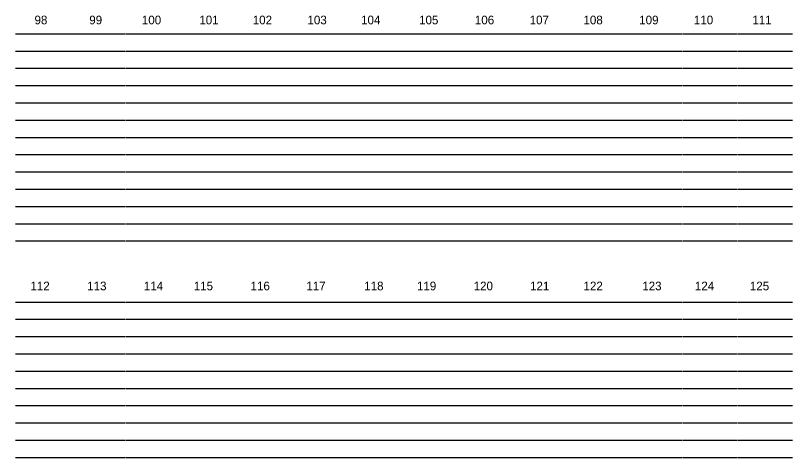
# Model space of a CAD drawing. Extents: x 11193 to 12507, y 10092 to 10555.
# Drawn here: x 11449.1 to 11644.1, y 10442.7 to 10553.6 of the extents above; entities that cross this region are included whole.
import ezdxf

# ---------------------------------------------------------------- set-up
doc = ezdxf.new("R2010")
doc.units = 0
doc.layers.add('Level 2', color=7, linetype='Continuous')

msp = doc.modelspace()

# ---------------------------------------------------------------- linework, layer by layer
at = {"layer": 'Level 2'}
for p, q in [((11449.15, 10549.04), (11463.08, 10549.04)), ((11463.2, 10549.04), (11476.76, 10549.04)), ((11476.87, 10549.04), (11490.84, 10549.04)), ((11490.96, 10549.04), (11504.92, 10549.04)), ((11505.04, 10549.04), (11518.81, 10549.04)), ((11518.92, 10549.04), (11532.69, 10549.04)), ((11532.79, 10549.04), (11546.77, 10549.04)), ((11546.87, 10549.04), (11560.65, 10549.04)), ((11560.75, 10549.04), (11574.74, 10549.04)), ((11574.84, 10549.04), (11588.61, 10549.04)), ((11588.71, 10549.04), (11602.29, 10549.04)), ((11602.39, 10549.04), (11616.37, 10549.04)), ((11616.47, 10549.04), (11630.25, 10549.04)), ((11630.36, 10549.04), (11644.09, 10549.04)), ((11449.15, 10544.71), (11463.08, 10544.71)), ((11463.2, 10544.71), (11476.76, 10544.71)), ((11476.87, 10544.71), (11490.84, 10544.71)), ((11490.96, 10544.71), (11504.92, 10544.71)), ((11505.04, 10544.71), (11518.81, 10544.71)), ((11518.92, 10544.71), (11532.69, 10544.71)), ((11532.79, 10544.71), (11546.77, 10544.71)), ((11546.87, 10544.71), (11560.65, 10544.71)), ((11560.75, 10544.71), (11574.74, 10544.71)), ((11574.84, 10544.71), (11588.61, 10544.71)), ((11588.71, 10544.71), (11602.29, 10544.71)), ((11602.39, 10544.71), (11616.37, 10544.71)), ((11616.47, 10544.71), (11630.25, 10544.71)), ((11630.36, 10544.71), (11644.09, 10544.71)), ((11449.15, 10540.37), (11463.08, 10540.37)), ((11463.2, 10540.37), (11476.76, 10540.37)), ((11476.87, 10540.37), (11490.84, 10540.37)), ((11490.96, 10540.37), (11504.92, 10540.37)), ((11505.04, 10540.37), (11518.81, 10540.37)), ((11518.92, 10540.37), (11532.69, 10540.37)), ((11532.79, 10540.37), (11546.77, 10540.37)), ((11546.87, 10540.37), (11560.65, 10540.37)), ((11560.75, 10540.37), (11574.74, 10540.37)), ((11574.84, 10540.37), (11588.61, 10540.37)), ((11588.71, 10540.37), (11602.29, 10540.37)), ((11602.39, 10540.37), (11616.37, 10540.37)), ((11616.47, 10540.37), (11630.25, 10540.37)), ((11630.36, 10540.37), (11644.09, 10540.37)), ((11449.15, 10536.04), (11463.08, 10536.04)), ((11463.2, 10536.04), (11476.76, 10536.04)), ((11476.87, 10536.04), (11490.84, 10536.04)), ((11490.96, 10536.04), (11504.92, 10536.04)), ((11505.04, 10536.04), (11518.81, 10536.04)), ((11518.92, 10536.04), (11532.69, 10536.04)), ((11532.79, 10536.04), (11546.77, 10536.04)), ((11546.87, 10536.04), (11560.65, 10536.04)), ((11560.75, 10536.04), (11574.74, 10536.04)), ((11574.84, 10536.04), (11588.61, 10536.04)), ((11588.71, 10536.04), (11602.29, 10536.04)), ((11602.39, 10536.04), (11616.37, 10536.04)), ((11616.47, 10536.04), (11630.25, 10536.04)), ((11630.36, 10536.04), (11644.09, 10536.04)), ((11449.15, 10531.71), (11463.08, 10531.71)), ((11463.2, 10531.71), (11476.76, 10531.71)), ((11476.87, 10531.71), (11490.84, 10531.71)), ((11490.96, 10531.71), (11504.92, 10531.71)), ((11505.04, 10531.71), (11518.81, 10531.71)), ((11518.92, 10531.71), (11532.69, 10531.71)), ((11532.79, 10531.71), (11546.77, 10531.71)), ((11546.87, 10531.71), (11560.65, 10531.71)), ((11560.75, 10531.71), (11574.74, 10531.71)), ((11574.84, 10531.71), (11588.61, 10531.71)), ((11588.71, 10531.71), (11602.29, 10531.71)), ((11602.39, 10531.71), (11616.37, 10531.71)), ((11616.47, 10531.71), (11630.25, 10531.71)), ((11630.36, 10531.71), (11644.09, 10531.71)), ((11449.15, 10527.38), (11463.08, 10527.38)), ((11463.2, 10527.38), (11476.76, 10527.38)), ((11476.87, 10527.38), (11490.84, 10527.38)), ((11490.96, 10527.38), (11504.92, 10527.38)), ((11505.04, 10527.38), (11518.81, 10527.38)), ((11518.92, 10527.38), (11532.69, 10527.38)), ((11532.79, 10527.38), (11546.77, 10527.38)), ((11546.87, 10527.38), (11560.65, 10527.38)), ((11560.75, 10527.38), (11574.74, 10527.38)), ((11574.84, 10527.38), (11588.61, 10527.38)), ((11588.71, 10527.38), (11602.29, 10527.38)), ((11602.39, 10527.38), (11616.37, 10527.38)), ((11616.47, 10527.38), (11630.25, 10527.38)), ((11630.36, 10527.38), (11644.09, 10527.38)), ((11449.15, 10523.05), (11463.08, 10523.05)), ((11463.2, 10523.05), (11476.76, 10523.05)), ((11476.87, 10523.05), (11490.84, 10523.05)), ((11490.96, 10523.05), (11504.92, 10523.05)), ((11505.04, 10523.05), (11518.81, 10523.05)), ((11518.92, 10523.05), (11532.69, 10523.05)), ((11532.79, 10523.05), (11546.77, 10523.05)), ((11546.87, 10523.05), (11560.65, 10523.05)), ((11560.75, 10523.05), (11574.74, 10523.05)), ((11574.84, 10523.05), (11588.61, 10523.05)), ((11588.71, 10523.05), (11602.29, 10523.05)), ((11602.39, 10523.05), (11616.37, 10523.05)), ((11616.47, 10523.05), (11630.25, 10523.05)), ((11630.36, 10523.05), (11644.09, 10523.05)), ((11449.15, 10518.71), (11463.08, 10518.71)), ((11463.2, 10518.71), (11476.76, 10518.71)), ((11476.87, 10518.71), (11490.84, 10518.71)), ((11490.96, 10518.71), (11504.92, 10518.71)), ((11505.04, 10518.71), (11518.81, 10518.71)), ((11518.92, 10518.71), (11532.69, 10518.71)), ((11532.79, 10518.71), (11546.77, 10518.71)), ((11546.87, 10518.71), (11560.65, 10518.71)), ((11560.75, 10518.71), (11574.74, 10518.71)), ((11574.84, 10518.71), (11588.61, 10518.71)), ((11588.71, 10518.71), (11602.29, 10518.71)), ((11602.39, 10518.71), (11616.37, 10518.71)), ((11616.47, 10518.71), (11630.25, 10518.71)), ((11630.36, 10518.71), (11644.09, 10518.71)), ((11449.15, 10514.38), (11463.08, 10514.38)), ((11463.2, 10514.38), (11476.76, 10514.38)), ((11476.87, 10514.38), (11490.84, 10514.38)), ((11490.96, 10514.38), (11504.92, 10514.38)), ((11505.04, 10514.38), (11518.81, 10514.38)), ((11518.92, 10514.38), (11532.69, 10514.38)), ((11532.79, 10514.38), (11546.77, 10514.38)), ((11546.87, 10514.38), (11560.65, 10514.38)), ((11560.75, 10514.38), (11574.74, 10514.38)), ((11574.84, 10514.38), (11588.61, 10514.38)), ((11588.71, 10514.38), (11602.29, 10514.38)), ((11602.39, 10514.38), (11616.37, 10514.38)), ((11616.47, 10514.38), (11630.25, 10514.38)), ((11630.36, 10514.38), (11644.09, 10514.38)), ((11449.15, 10510.05), (11463.08, 10510.05)), ((11463.2, 10510.05), (11476.76, 10510.05)), ((11476.87, 10510.05), (11490.84, 10510.05)), ((11490.96, 10510.05), (11504.92, 10510.05)), ((11505.04, 10510.05), (11518.81, 10510.05)), ((11518.92, 10510.05), (11532.69, 10510.05)), ((11532.79, 10510.05), (11546.77, 10510.05)), ((11546.87, 10510.05), (11560.65, 10510.05)), ((11560.75, 10510.05), (11574.74, 10510.05)), ((11574.84, 10510.05), (11588.61, 10510.05)), ((11588.71, 10510.05), (11602.29, 10510.05)), ((11602.39, 10510.05), (11616.37, 10510.05)), ((11616.47, 10510.05), (11630.25, 10510.05)), ((11630.36, 10510.05), (11644.09, 10510.05)), ((11449.15, 10505.72), (11463.08, 10505.72)), ((11463.2, 10505.72), (11476.76, 10505.72)), ((11476.87, 10505.72), (11490.84, 10505.72)), ((11490.96, 10505.72), (11504.92, 10505.72)), ((11505.04, 10505.72), (11518.81, 10505.72)), ((11518.92, 10505.72), (11532.69, 10505.72)), ((11532.79, 10505.72), (11546.77, 10505.72)), ((11546.87, 10505.72), (11560.65, 10505.72)), ((11560.75, 10505.72), (11574.74, 10505.72)), ((11574.84, 10505.72), (11588.61, 10505.72)), ((11588.71, 10505.72), (11602.29, 10505.72)), ((11602.39, 10505.72), (11616.37, 10505.72)), ((11616.47, 10505.72), (11630.25, 10505.72)), ((11630.36, 10505.72), (11644.09, 10505.72)), ((11449.15, 10501.39), (11463.08, 10501.39)), ((11463.2, 10501.39), (11476.76, 10501.39)), ((11476.87, 10501.39), (11490.84, 10501.39)), ((11490.96, 10501.39), (11504.92, 10501.39)), ((11505.04, 10501.39), (11518.81, 10501.39)), ((11518.92, 10501.39), (11532.69, 10501.39)), ((11532.79, 10501.39), (11546.77, 10501.39)), ((11546.87, 10501.39), (11560.65, 10501.39)), ((11560.75, 10501.39), (11574.74, 10501.39)), ((11574.84, 10501.39), (11588.61, 10501.39)), ((11588.71, 10501.39), (11602.29, 10501.39)), ((11602.39, 10501.39), (11616.37, 10501.39)), ((11616.47, 10501.39), (11630.25, 10501.39)), ((11630.36, 10501.39), (11644.09, 10501.39)), ((11449.15, 10497.05), (11463.08, 10497.05)), ((11463.2, 10497.05), (11476.76, 10497.05)), ((11476.87, 10497.05), (11490.84, 10497.05)), ((11490.96, 10497.05), (11504.92, 10497.05)), ((11505.04, 10497.05), (11518.81, 10497.05)), ((11518.92, 10497.05), (11532.69, 10497.05)), ((11532.79, 10497.05), (11546.77, 10497.05)), ((11546.87, 10497.05), (11560.65, 10497.05)), ((11560.75, 10497.05), (11574.74, 10497.05)), ((11574.84, 10497.05), (11588.61, 10497.05)), ((11588.71, 10497.05), (11602.29, 10497.05)), ((11602.39, 10497.05), (11616.37, 10497.05)), ((11616.47, 10497.05), (11630.25, 10497.05)), ((11630.36, 10497.05), (11644.09, 10497.05)), ((11449.15, 10481.72), (11463.08, 10481.72)), ((11463.2, 10481.72), (11476.76, 10481.72)), ((11476.87, 10481.72), (11490.84, 10481.72)), ((11490.96, 10481.72), (11504.92, 10481.72)), ((11505.04, 10481.72), (11518.81, 10481.72)), ((11518.92, 10481.72), (11532.69, 10481.72)), ((11532.79, 10481.72), (11546.77, 10481.72)), ((11546.87, 10481.72), (11560.65, 10481.72)), ((11560.75, 10481.72), (11574.74, 10481.72)), ((11574.84, 10481.72), (11588.61, 10481.72)), ((11588.71, 10481.72), (11602.29, 10481.72)), ((11602.39, 10481.72), (11616.37, 10481.72)), ((11616.47, 10481.72), (11630.25, 10481.72)), ((11630.36, 10481.72), (11644.09, 10481.72)), ((11449.15, 10477.39), (11463.08, 10477.39)), ((11463.2, 10477.39), (11476.76, 10477.39)), ((11476.87, 10477.39), (11490.84, 10477.39)), ((11490.96, 10477.39), (11504.92, 10477.39)), ((11505.04, 10477.39), (11518.81, 10477.39)), ((11518.92, 10477.39), (11532.69, 10477.39)), ((11532.79, 10477.39), (11546.77, 10477.39)), ((11546.87, 10477.39), (11560.65, 10477.39)), ((11560.75, 10477.39), (11574.74, 10477.39)), ((11574.84, 10477.39), (11588.61, 10477.39)), ((11588.71, 10477.39), (11602.29, 10477.39)), ((11602.39, 10477.39), (11616.37, 10477.39)), ((11616.47, 10477.39), (11630.25, 10477.39)), ((11630.36, 10477.39), (11644.09, 10477.39)), ((11449.15, 10473.06), (11463.08, 10473.06)), ((11463.2, 10473.06), (11476.76, 10473.06)), ((11476.87, 10473.06), (11490.84, 10473.06)), ((11490.96, 10473.06), (11504.92, 10473.06)), ((11505.04, 10473.06), (11518.81, 10473.06)), ((11518.92, 10473.06), (11532.69, 10473.06)), ((11532.79, 10473.06), (11546.77, 10473.06)), ((11546.87, 10473.06), (11560.65, 10473.06)), ((11560.75, 10473.06), (11574.74, 10473.06)), ((11574.84, 10473.06), (11588.61, 10473.06)), ((11588.71, 10473.06), (11602.29, 10473.06)), ((11602.39, 10473.06), (11616.37, 10473.06)), ((11616.47, 10473.06), (11630.25, 10473.06)), ((11630.36, 10473.06), (11644.09, 10473.06)), ((11449.15, 10468.72), (11463.08, 10468.72)), ((11463.2, 10468.72), (11476.76, 10468.72)), ((11476.87, 10468.72), (11490.84, 10468.72)), ((11490.96, 10468.72), (11504.92, 10468.72)), ((11505.04, 10468.72), (11518.81, 10468.72)), ((11518.92, 10468.72), (11532.69, 10468.72)), ((11532.79, 10468.72), (11546.77, 10468.72)), ((11546.87, 10468.72), (11560.65, 10468.72)), ((11560.75, 10468.72), (11574.74, 10468.72)), ((11574.84, 10468.72), (11588.61, 10468.72)), ((11588.71, 10468.72), (11602.29, 10468.72)), ((11602.39, 10468.72), (11616.37, 10468.72)), ((11616.47, 10468.72), (11630.25, 10468.72)), ((11630.36, 10468.72), (11644.09, 10468.72)), ((11449.15, 10464.39), (11463.08, 10464.39)), ((11463.2, 10464.39), (11476.76, 10464.39)), ((11476.87, 10464.39), (11490.84, 10464.39)), ((11490.96, 10464.39), (11504.92, 10464.39)), ((11505.04, 10464.39), (11518.81, 10464.39)), ((11518.92, 10464.39), (11532.69, 10464.39)), ((11532.79, 10464.39), (11546.77, 10464.39)), ((11546.87, 10464.39), (11560.65, 10464.39)), ((11560.75, 10464.39), (11574.74, 10464.39)), ((11574.84, 10464.39), (11588.61, 10464.39)), ((11588.71, 10464.39), (11602.29, 10464.39)), ((11602.39, 10464.39), (11616.37, 10464.39)), ((11616.47, 10464.39), (11630.25, 10464.39)), ((11630.36, 10464.39), (11644.09, 10464.39)), ((11449.15, 10460.06), (11463.08, 10460.06)), ((11463.2, 10460.06), (11476.76, 10460.06)), ((11476.87, 10460.06), (11490.84, 10460.06)), ((11490.96, 10460.06), (11504.92, 10460.06)), ((11505.04, 10460.06), (11518.81, 10460.06)), ((11518.92, 10460.06), (11532.69, 10460.06)), ((11532.79, 10460.06), (11546.77, 10460.06)), ((11546.87, 10460.06), (11560.65, 10460.06)), ((11560.75, 10460.06), (11574.74, 10460.06)), ((11574.84, 10460.06), (11588.61, 10460.06)), ((11588.71, 10460.06), (11602.29, 10460.06)), ((11602.39, 10460.06), (11616.37, 10460.06)), ((11616.47, 10460.06), (11630.25, 10460.06)), ((11630.36, 10460.06), (11644.09, 10460.06)), ((11449.15, 10455.73), (11463.08, 10455.73)), ((11463.2, 10455.73), (11476.76, 10455.73)), ((11476.87, 10455.73), (11490.84, 10455.73)), ((11490.96, 10455.73), (11504.92, 10455.73)), ((11505.04, 10455.73), (11518.81, 10455.73)), ((11518.92, 10455.73), (11532.69, 10455.73)), ((11532.79, 10455.73), (11546.77, 10455.73)), ((11546.87, 10455.73), (11560.65, 10455.73)), ((11560.75, 10455.73), (11574.74, 10455.73)), ((11574.84, 10455.73), (11588.61, 10455.73)), ((11588.71, 10455.73), (11602.29, 10455.73)), ((11602.39, 10455.73), (11616.37, 10455.73)), ((11616.47, 10455.73), (11630.25, 10455.73)), ((11630.36, 10455.73), (11644.09, 10455.73)), ((11449.15, 10451.4), (11463.08, 10451.4)), ((11463.2, 10451.4), (11476.76, 10451.4)), ((11476.87, 10451.4), (11490.84, 10451.4)), ((11490.96, 10451.4), (11504.92, 10451.4)), ((11505.04, 10451.4), (11518.81, 10451.4)), ((11518.92, 10451.4), (11532.69, 10451.4)), ((11532.79, 10451.4), (11546.77, 10451.4)), ((11546.87, 10451.4), (11560.65, 10451.4)), ((11560.75, 10451.4), (11574.74, 10451.4)), ((11574.84, 10451.4), (11588.61, 10451.4)), ((11588.71, 10451.4), (11602.29, 10451.4)), ((11602.39, 10451.4), (11616.37, 10451.4)), ((11616.47, 10451.4), (11630.25, 10451.4)), ((11630.36, 10451.4), (11644.09, 10451.4)), ((11449.15, 10447.06), (11463.08, 10447.06)), ((11463.2, 10447.06), (11476.76, 10447.06)), ((11476.87, 10447.06), (11490.84, 10447.06)), ((11490.96, 10447.06), (11504.92, 10447.06)), ((11505.04, 10447.06), (11518.81, 10447.06)), ((11518.92, 10447.06), (11532.69, 10447.06)), ((11532.79, 10447.06), (11546.77, 10447.06)), ((11546.87, 10447.06), (11560.65, 10447.06)), ((11560.75, 10447.06), (11574.74, 10447.06)), ((11574.84, 10447.06), (11588.61, 10447.06)), ((11588.71, 10447.06), (11602.29, 10447.06)), ((11602.39, 10447.06), (11616.37, 10447.06)), ((11616.47, 10447.06), (11630.25, 10447.06)), ((11630.36, 10447.06), (11644.09, 10447.06)), ((11449.15, 10442.73), (11463.08, 10442.73)), ((11463.2, 10442.73), (11476.76, 10442.73)), ((11476.87, 10442.73), (11490.84, 10442.73)), ((11490.96, 10442.73), (11504.92, 10442.73)), ((11505.04, 10442.73), (11518.81, 10442.73)), ((11518.92, 10442.73), (11532.69, 10442.73)), ((11532.79, 10442.73), (11546.77, 10442.73)), ((11546.87, 10442.73), (11560.65, 10442.73)), ((11560.75, 10442.73), (11574.74, 10442.73)), ((11574.84, 10442.73), (11588.61, 10442.73)), ((11588.71, 10442.73), (11602.29, 10442.73)), ((11602.39, 10442.73), (11616.37, 10442.73)), ((11616.47, 10442.73), (11630.25, 10442.73)), ((11630.36, 10442.73), (11644.09, 10442.73))]:
    msp.add_line(p, q, dxfattribs=at)

# ---------------------------------------------------------------- texts
for s, p in [('98', (11453.91, 10551.41)), ('99', (11467.65, 10551.41)), ('100', (11480.85, 10551.41)), ('101', (11495.26, 10551.41)), ('102', (11508.67, 10551.41)), ('103', (11522.4, 10551.41)), ('104', (11535.85, 10551.41)), ('105', (11550.41, 10551.41)), ('106', (11564.4, 10551.41)), ('107', (11578.14, 10551.41)), ('108', (11591.65, 10551.41)), ('109', (11605.64, 10551.41)), ('110', (11619.36, 10551.41)), ('111', (11634.02, 10551.41)), ('112', (11452.89, 10484.67)), ('113', (11467.13, 10484.67)), ('114', (11481.35, 10484.67)), ('115', (11493.87, 10484.67)), ('116', (11508.12, 10484.67)), ('117', (11522.11, 10484.67)), ('118', (11536.64, 10484.67)), ('119', (11549.87, 10484.67)), ('120', (11564.1, 10484.67)), ('121', (11578.25, 10484.67)), ('122', (11591.66, 10484.67)), ('123', (11606.41, 10484.67)), ('124', (11619.61, 10484.67)), ('125', (11633.4, 10484.67))]:
    msp.add_text(s, height=2.17, dxfattribs=at).set_placement(p)

doc.saveas('drawing.dxf')
